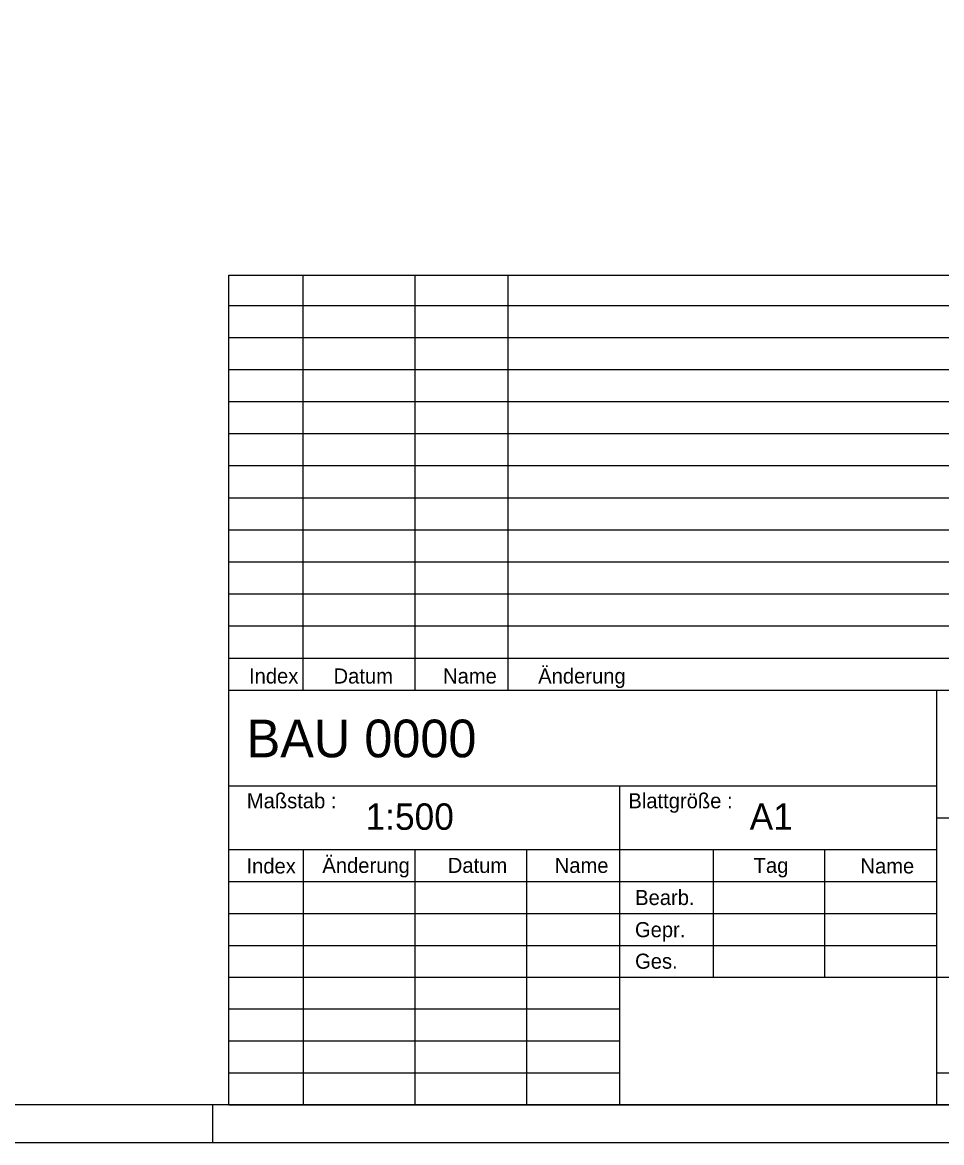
# Model space of a CAD drawing. Extents: x 0 to 420, y 0 to 297.
# Drawn here: x 315.4 to 376.3, y 0 to 74.2 of the extents above; entities that cross this region are included whole.
import ezdxf

# ---------------------------------------------------------------- set-up
doc = ezdxf.new("R2010")
doc.units = 0
doc.layers.add('90_Plankopf', color=7, linetype='Continuous')

msp = doc.modelspace()

# ---------------------------------------------------------------- linework, layer by layer
at = {"layer": '90_Plankopf'}
for p, q in [((329.06, 29.995), (329.06, 57.49)), ((329.06, 57.49), (418, 57.49)), ((334.001, 29.995), (334.001, 57.49)), ((341.413, 29.995), (341.413, 57.49)), ((347.59, 29.995), (347.59, 57.49)), ((329.06, 55.495), (418, 55.495)), ((329.06, 53.37), (418, 53.37)), ((329.06, 51.245), (418, 51.245)), ((329.06, 49.12), (418, 49.12)), ((329.06, 46.995), (418, 46.995)), ((329.06, 44.87), (418, 44.87)), ((329.06, 42.745), (418, 42.745)), ((329.06, 40.62), (418, 40.62)), ((329.06, 38.495), (418, 38.495)), ((329.06, 36.37), (418, 36.37)), ((329.06, 34.245), (418, 34.245)), ((329.06, 32.12), (418, 32.12)), ((329.06, 29.995), (418, 29.995)), ((329.06, 2.5), (329.06, 29.995)), ((329.06, 29.995), (418, 29.995)), ((376.001, 2.5), (376.001, 29.995)), ((329.06, 23.65), (376.001, 23.65)), ((355.001, 2.5), (355.001, 23.65)), ((376.001, 21.535), (418, 21.535)), ((329.06, 19.435), (376.001, 19.435)), ((334.001, 19.42), (334.001, 2.5)), ((341.413, 2.5), (341.413, 19.42)), ((348.825, 2.5), (348.825, 19.42)), ((361.177, 19.42), (361.177, 10.96)), ((368.589, 10.96), (368.589, 19.42)), ((329.06, 17.315), (376.001, 17.315)), ((329.06, 15.19), (376.001, 15.19)), ((329.06, 13.075), (376.001, 13.075)), ((329.06, 10.96), (376.001, 10.96)), ((329.06, 10.96), (376.001, 10.96)), ((355.001, 10.96), (376.001, 10.96)), ((376.001, 10.96), (418, 10.96)), ((355.001, 8.845), (329.06, 8.845)), ((355.001, 6.73), (329.06, 6.73)), ((329.06, 4.615), (355.001, 4.615)), ((376.001, 4.615), (418, 4.615)), ((328, 0), (328, 2.5)), ((418, 2.5), (329.06, 2.5)), ((329.06, 2.5), (355.001, 2.5)), ((334.9, 2.5), (418, 2.5)), ((334.9, 2.5), (418, 2.5))]:
    msp.add_line(p, q, dxfattribs=at)
for points in [[(0, 0), (420.5, 0), (420.5, 297), (0, 297)], [(12.5, 294.5), (418, 294.5), (418, 2.5), (12.5, 2.5)]]:
    msp.add_lwpolyline(points, close=True, dxfattribs=at)

# ---------------------------------------------------------------- texts
for s, height, p in [('Index', 1, (330.402, 30.428)), ('Datum', 1, (336.007, 30.428)), ('Name', 1, (343.269, 30.428)), ('Änderung', 1, (349.579, 30.428)), ('BAU 0000      ', 2.5, (330.245, 25.538)), ('Maßstab :', 1, (330.258, 22.158)), ('Blattgröße :', 0.99995, (355.558, 22.158)), ('1:500    ', 1.75, (338.131, 20.734)), ('A1       ', 1.75, (363.6, 20.734)), ('Index', 1, (330.235, 17.837)), ('Änderung', 1, (335.267, 17.875)), ('Datum', 1, (343.584, 17.875)), ('Name', 1, (350.673, 17.875)), ('Tag', 1, (363.862, 17.875)), ('Name', 1, (370.946, 17.837)), ('Bearb.', 1, (356.007, 15.745)), ('Gepr.', 1, (355.995, 13.615)), ('Ges.', 1, (356.002, 11.524))]:
    msp.add_text(s, height=height, dxfattribs=at).set_placement(p)

doc.saveas('drawing.dxf')
